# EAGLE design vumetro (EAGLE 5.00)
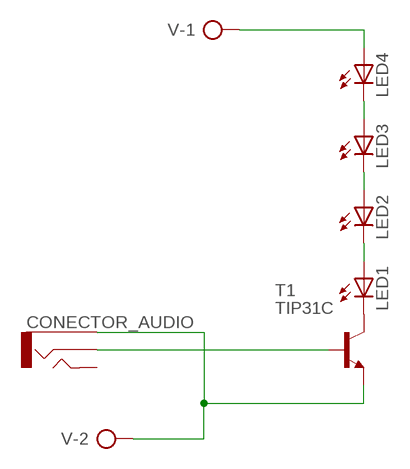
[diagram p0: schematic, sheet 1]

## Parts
CONECTOR_AUDIO  AUDIO-JACKPTH  [AUDIO-JACK]
LED1  LED10MM  [LED10MM]
LED2  LED10MM  [LED10MM]
LED3  LED10MM  [LED10MM]
LED4  LED10MM  [LED10MM]
T1  TIP31C  [TO220]
V  AK500/2  [AK500/2]

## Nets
GND: CONECTOR_AUDIO.1 T1.3(E) V.2
N$1: LED1.K(C) T1.2(C)
N$3: CONECTOR_AUDIO.2 T1.1(B)
N$4: LED3.A LED4.K(C)
N$5: LED2.A LED3.K(C)
N$6: LED1.A LED2.K(C)
N$7: LED4.A V.1
Unconnected: CONECTOR_AUDIO.5

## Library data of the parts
CONECTOR_AUDIO = SparkFun:AUDIO-JACK: 3.5mm Audio Jack Simple 3.5mm common PCB mount audio jack. SKU: PRT-08032
LED1-LED4 = led:LED: LED
T1 = transistor:TIP31: NPN Transistor Medium Power Linear Switching Applications Source: http://onsemi.com
V = con-ptr500:AK500/2: CONNECTOR

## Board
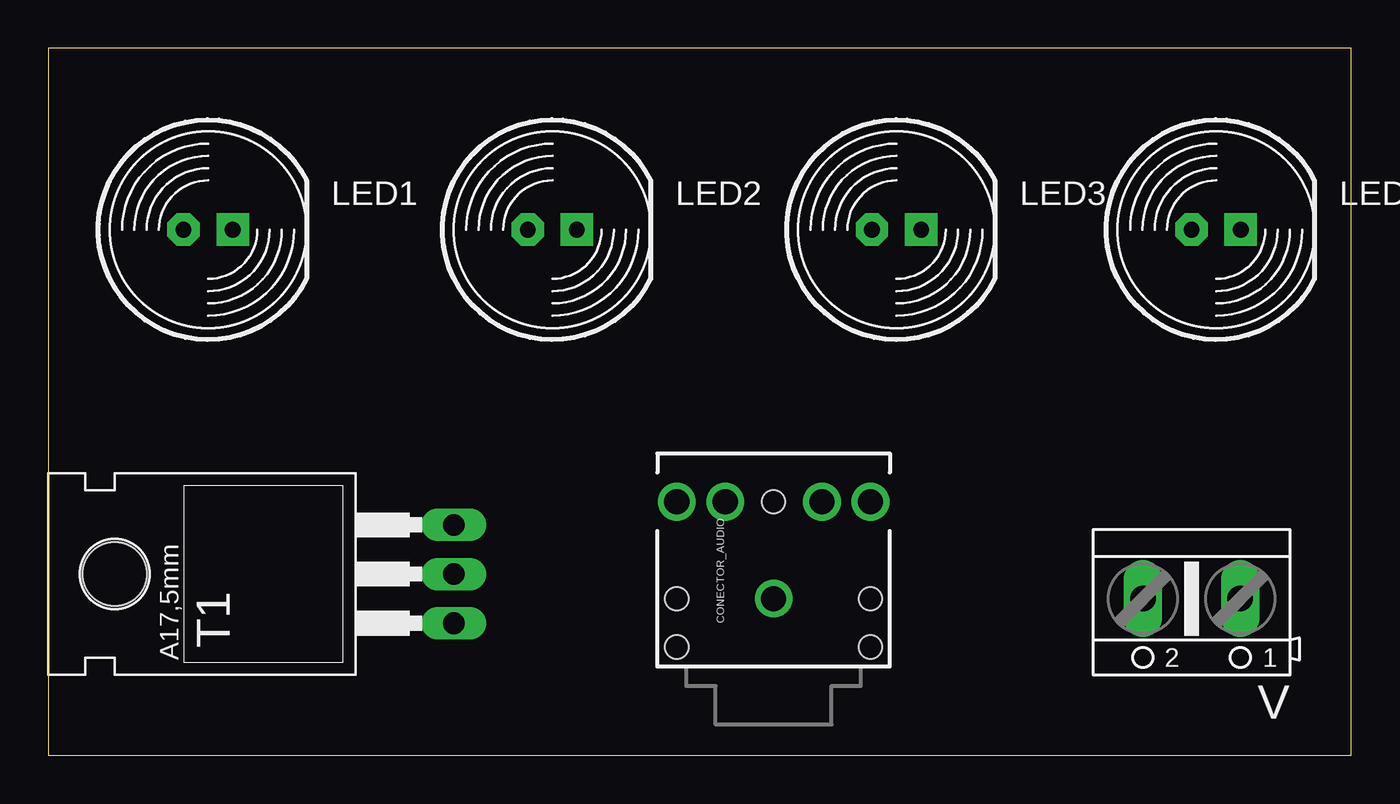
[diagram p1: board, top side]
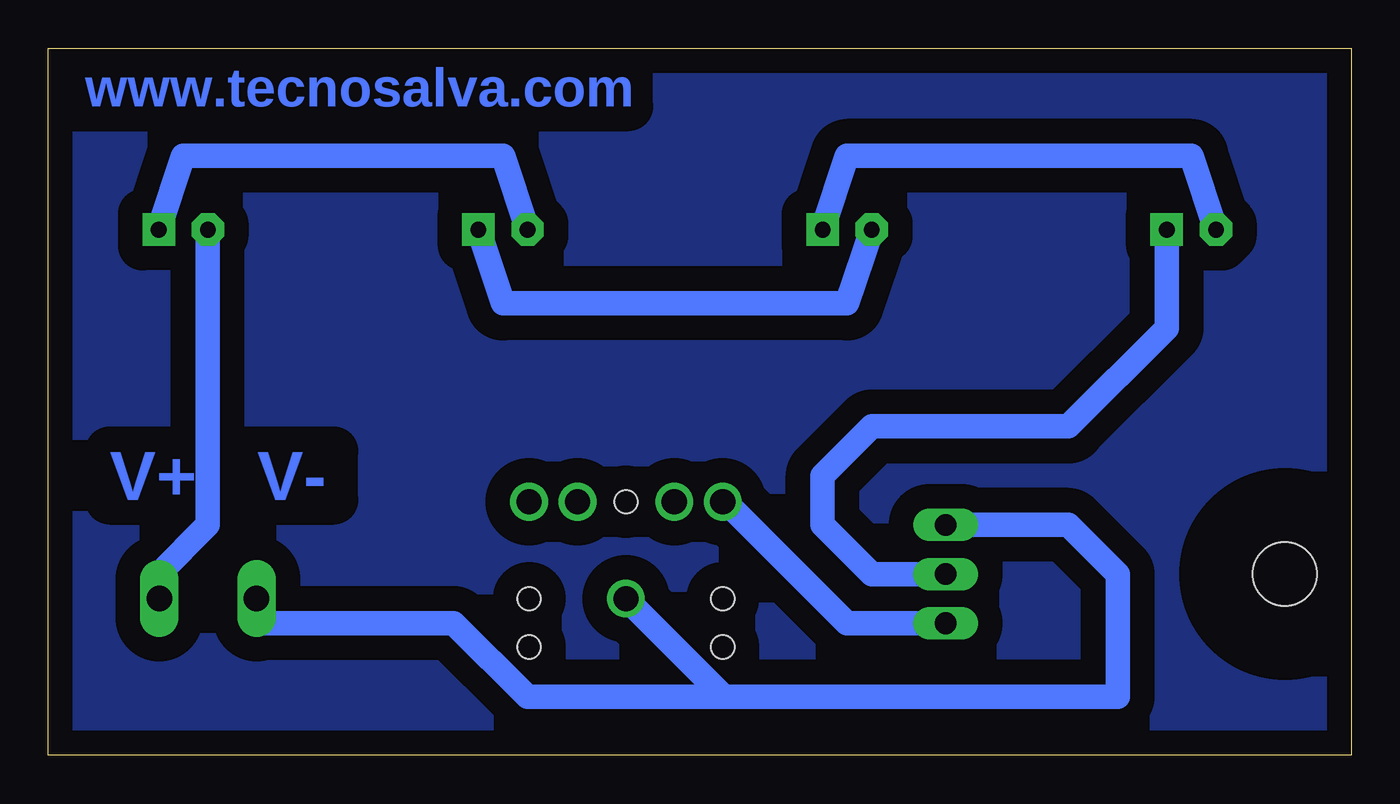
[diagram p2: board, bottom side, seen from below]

Size 67.29 x 36.5 mm. Coordinates in mm from the lower left corner, seen from the top.
Outline: 0,0 67.29,0 67.29,36.5 0,36.5 0,0
Copper layers (1*16): Top 0.035mm / dielectric 1.5mm / Bottom 0.035mm
Design rules: minimum track width 12mil, minimum drill 24mil, track to track 8mil, track to pad 8mil, pad to pad 8mil, via to via 8mil, smd to smd 8mil, copper to edge 40mil, drill to drill 8mil, minimum pad ring 10mil, minimum via ring 8mil, stop-mask expansion 4mil, vias tented up to drill 0mil, thermal gap 10mil

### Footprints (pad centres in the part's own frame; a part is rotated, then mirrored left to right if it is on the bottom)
AUDIO-JACK = drill 1.3: 1 0,0; 2 5,5; 3 5,2.5; 4 5,-2.5; 5 5,-5 | hole 1.2: 0,5; -2.5,5; -2.5,-5; 0,-5; 5,0
LED10MM = drill 0.813 pad 1.676 octagon: A -1.27,0 | drill 0.813 pad 1.676 square: K 1.27,0
TO220 = drill 1.118 long: 1 -2.54,-6.35; 2 0,-6.35; 3 2.54,-6.35 | hole 3.302: 0,11.176
AK500/2 = drill 1.321 long: 1 -2.515,0; 2 2.515,0

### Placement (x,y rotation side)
CONECTOR_AUDIO  37.46,8.09 90 top
LED1  8.25,27.14 0 top
LED2  26.03,27.14 0 top
LED3  43.81,27.14 0 top
LED4  60.32,27.14 0 top
T1  14.6,9.36 90 top
V  59.05,8.09 180 top

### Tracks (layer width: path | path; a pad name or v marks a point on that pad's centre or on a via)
GND
  Bottom 1.27: 32.38,3.01 CONECTOR_AUDIO.1 | 32.38,3.01 42.54,3.01 46.35,6.82 56.51,6.82 V.2 | 32.38,3.01 12.06,3.01 12.06,9.36 14.6,11.9 T1.3
N$1
  Bottom 1.27: T1.2 24.76,9.36 27.3,11.9 27.3,14.44 24.76,16.98 14.6,16.98 9.52,22.06 LED1.K
N$2
  pour Bottom (isolate 1.27): 0.63,36.03 0.63,0.47 66.67,0.47 66.67,36.03
N$3
  Bottom 0.305: 32.38,13.17 CONECTOR_AUDIO.2
  Bottom 1.27: 32.38,13.17 26.03,6.82 T1.1
N$4
  Bottom 1.27: LED3.A 43.81,30.95 60.32,30.95 LED4.K
N$5
  Bottom 1.27: LED2.A 26.03,23.33 43.81,23.33 LED3.K
N$6
  Bottom 1.27: LED1.A 8.25,30.95 26.03,30.95 LED2.K
N$7
  Bottom 1.27: LED4.A 59.05,11.9 61.59,9.36 V.1

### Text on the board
Bottom: www.tecnosalva.com | V- | V+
